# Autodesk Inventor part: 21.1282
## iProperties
Created: 2006-02
Part Number: 21.1282
Material: Steel, Mild
Description: M8X70 SHCS
Document SubType Name: Modeling
Standard: DIN 7984
Designer: Andy Moles
Standards Organization: DIN
Language: en-US
Size Designation: M8 x 60
Categories: <MemberInstance><Categories><Category DisplayName="Fasteners" InternalName="e4da775c-781d-43d5-af7c-5136215cf5a6" Mnemonic="FSTN"><Category DisplayName="Bolts"
Mass: 32.0174 g
Surface Area: 22.7431 cm^2
Volume: 4.07346 cm^3
Density: 7.86 g/cm^3
Vendor: S
Author: Andy Moles
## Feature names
1. Body [Revolution]
2. Slot [Extrusion]
3. Fillet1
4. Chamfer1
